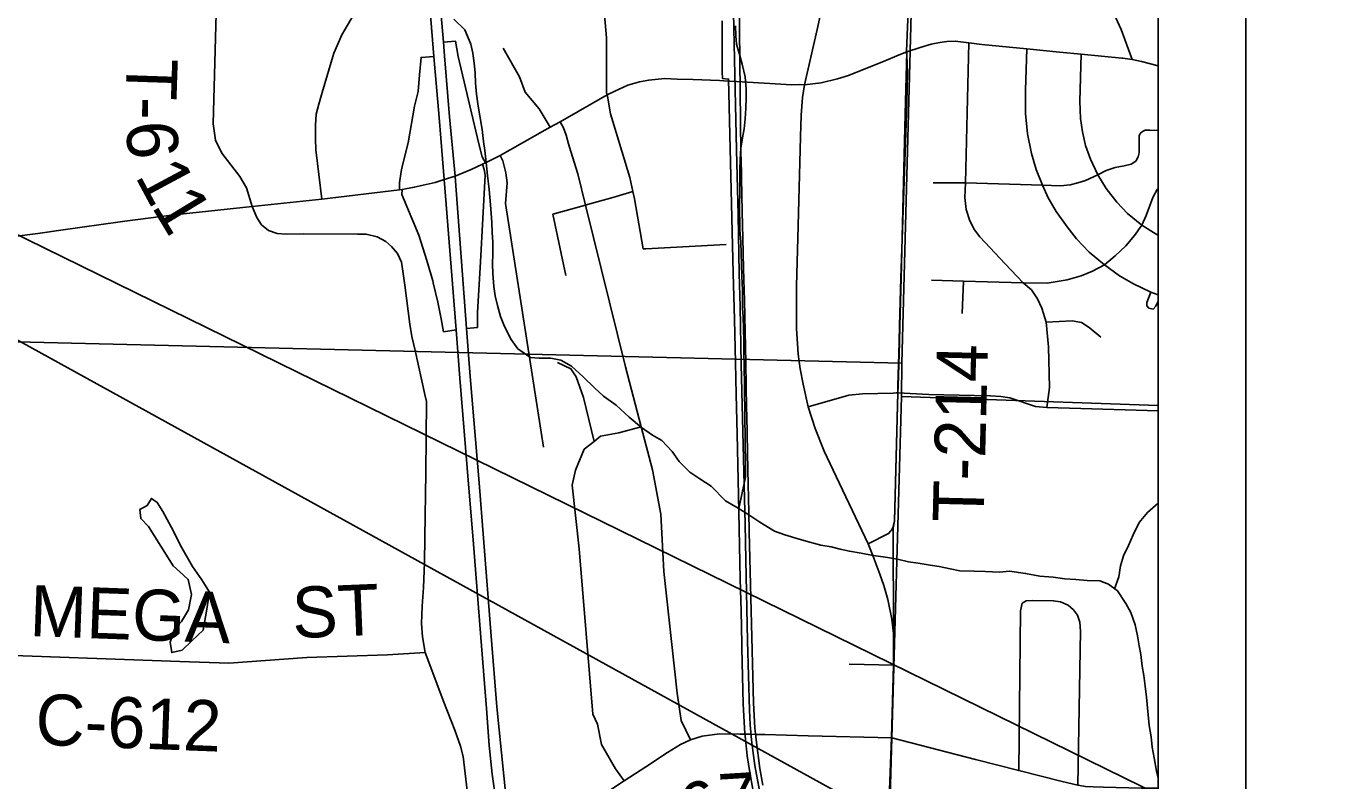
# Model space of a CAD drawing. Extents: x 0 to 34, y 0 to 22.
# Drawn here: x 8.376 to 9.827, y 18.372 to 19.213 of the extents above; entities that cross this region are included whole.
import ezdxf

# ---------------------------------------------------------------- set-up
doc = ezdxf.new("R2010")
doc.units = 0
for name, color, linetype in [('GM_X_City_Street', 7, 'Continuous'), ('GM_X_Corporation', 7, 'Continuous'), ('GM_X_County_Road', 7, 'Continuous'), ('GM_X_County_Road_Text', 7, 'Continuous'), ('GM_X_Interchange_Ramps', 7, 'Continuous'), ('GM_X_Interstate_Route', 7, 'Continuous'), ('GM_X_Minor_Lake', 7, 'Continuous'), ('GM_X_Minor_River', 7, 'Continuous'), ('GM_X_Rail_Line', 7, 'Continuous'), ('GM_X_Township_Road', 7, 'Continuous'), ('GM_X_Township_Road_Text', 7, 'Continuous'), ('SH_Data', 7, 'Continuous'), ('SH_Text', 7, 'Continuous')]:
    doc.layers.add(name, color=color, linetype=linetype)

msp = doc.modelspace()

# ---------------------------------------------------------------- linework, layer by layer
at = {"layer": 'GM_X_City_Street'}
msp.add_line((9.4188, 18.8933), (9.4202, 18.9294), dxfattribs=at)
for points in [[(9.5132, 18.7884), (9.516, 18.8109), (9.515, 18.8562), (9.5124, 18.8837), (9.5076, 18.899), (9.5025, 18.9094), (9.4958, 18.9195), (9.4867, 18.9274), (9.4668, 18.9487), (9.4385, 18.9785), (9.4325, 18.9864), (9.4274, 18.9964), (9.4231, 19.0089), (9.4218, 19.0224), (9.4224, 19.0387), (9.426, 19.1948)], [(9.637, 18.914), (9.6289, 18.9171), (9.6095, 18.9264), (9.5941, 18.9352), (9.5773, 18.9475), (9.5603, 18.9617), (9.546, 18.9764), (9.5356, 18.9896), (9.5235, 19.007), (9.5147, 19.0219), (9.5082, 19.0363), (9.5012, 19.0536), (9.4958, 19.0715), (9.4915, 19.0932), (9.4894, 19.1159), (9.4892, 19.1421), (9.4909, 19.1879)], [(9.637, 18.9806), (9.6348, 18.9817), (9.619, 18.9917), (9.6031, 19.0047), (9.5911, 19.0173), (9.5791, 19.0323), (9.5699, 19.0476), (9.5616, 19.065), (9.5561, 19.0803), (9.5527, 19.0957), (9.5505, 19.1103), (9.5497, 19.1296), (9.5513, 19.182)], [(9.3865, 19.0387), (9.4224, 19.0387), (9.5082, 19.0363), (9.5284, 19.0356), (9.539, 19.0365), (9.5478, 19.0386), (9.556, 19.0414), (9.5699, 19.0476), (9.5792, 19.0524), (9.5891, 19.0559), (9.5992, 19.0577), (9.6071, 19.0594), (9.6121, 19.0629), (9.6149, 19.0677), (9.6159, 19.0723), (9.6159, 19.0869), (9.6159, 19.091), (9.6172, 19.0937), (9.6196, 19.096), (9.6228, 19.0973), (9.6279, 19.0974), (9.637, 19.0972)], [(9.3847, 18.9305), (9.4202, 18.9294), (9.4867, 18.9274), (9.5133, 18.927), (9.5356, 18.9306), (9.5514, 18.9352), (9.5638, 18.9405), (9.5773, 18.9475), (9.5894, 18.9573), (9.6011, 18.9685), (9.6108, 18.98), (9.619, 18.9917), (9.6238, 19.0025), (9.6313, 19.0223), (9.6362, 19.0314), (9.637, 19.0321)], [(9.6289, 18.9171), (9.6245, 18.9053), (9.6246, 18.9018), (9.6266, 18.8993), (9.6316, 18.8982), (9.6347, 18.9015), (9.637, 18.9068)], [(9.5124, 18.8837), (9.5414, 18.8849), (9.5517, 18.8832), (9.5603, 18.8775), (9.5732, 18.8669)], [(9.4817, 18.384), (9.4837, 18.5619), (9.4854, 18.5705)], [(9.4854, 18.5705), (9.4899, 18.573), (9.4967, 18.5734), (9.5202, 18.5733), (9.5282, 18.5719), (9.5367, 18.5682), (9.5429, 18.5632)], [(9.5477, 18.3676), (9.5505, 18.5393), (9.5497, 18.5492), (9.5474, 18.5571), (9.5429, 18.5632)]]:
    msp.add_lwpolyline(points, dxfattribs=at)
at = {"layer": 'GM_X_Corporation'}
for points in [[(7.1023, 20.9204), (2.837, 20.9204), (2.837, 14.1204), (9.637, 14.1204), (9.637, 20.9204), (9.4036, 20.9204), (9.4022, 20.8667), (9.2273, 20.8723), (9.1354, 20.8749), (9.124, 20.8753), (8.9858, 20.878), (8.9676, 20.8785), (8.8663, 20.881), (8.6259, 20.8892), (8.5535, 20.8914), (8.5421, 20.8915), (8.4667, 20.8934), (8.0602, 20.9055), (7.9522, 20.9084), (7.1104, 20.9188)], [(8.3589, 19.8763), (9.3789, 19.8558), (9.3773, 19.7981), (9.3514, 18.838), (8.3333, 18.8624)], [(9.637, 18.7908), (9.637, 19.791), (9.3773, 19.7981), (9.3514, 18.838), (9.3511, 18.8009)], [(8.3333, 18.8624), (9.3514, 18.838), (9.3511, 18.8009), (9.3232, 17.8175), (8.3013, 17.8445)], [(9.637, 17.7759), (9.637, 18.7908), (9.3511, 18.8009), (9.3232, 17.8175), (9.3224, 17.7834)]]:
    msp.add_lwpolyline(points, close=True, dxfattribs=at)
for points in [[(9.637, 14.7553), (9.637, 20.8621)], [(9.3877, 20.1427), (9.3802, 19.8717), (9.377, 19.7721), (9.3757, 19.7325), (9.3706, 19.5177), (9.3568, 19.1851), (9.3573, 19.1731), (9.3575, 19.1703), (9.3577, 19.163), (9.3575, 19.1426), (9.3568, 19.1161), (9.3505, 18.9331), (9.349, 18.88), (9.3486, 18.8618), (9.3482, 18.8485), (9.3472, 18.8129), (9.347, 18.8053), (9.3432, 18.6624), (9.3419, 18.6564), (9.3421, 18.534), (9.3421, 18.502), (9.3401, 18.421), (9.3264, 18.0621)], [(9.3264, 18.0621), (9.3401, 18.421), (9.3421, 18.502), (9.3421, 18.534), (9.3419, 18.6564), (9.3432, 18.6624), (9.347, 18.8053), (9.3472, 18.8129), (9.3482, 18.8485), (9.3486, 18.8618), (9.349, 18.88), (9.3505, 18.9331), (9.3568, 19.1161), (9.3575, 19.1426), (9.3577, 19.163), (9.3575, 19.1703), (9.3573, 19.1731), (9.3568, 19.1851), (9.3706, 19.5177), (9.3757, 19.7325), (9.377, 19.7721), (9.3802, 19.8717), (9.3877, 20.1427)], [(9.1965, 18.3677), (9.1931, 18.3862), (9.1891, 18.4184), (9.1884, 18.4252), (9.1878, 18.4313), (9.1863, 18.4596), (9.1826, 18.6057), (9.1815, 18.6499), (9.181, 18.672), (9.18, 18.7186), (9.1786, 18.7797), (9.1784, 18.7876), (9.1776, 18.8382), (9.176, 18.9076), (9.1752, 18.9433), (9.1744, 18.9773), (9.1737, 19.0066), (9.1728, 19.0445), (9.1727, 19.0501), (9.1722, 19.0732), (9.1704, 19.2433)], [(9.1511, 19.2193), (9.1514, 19.1601), (9.1515, 19.1573), (9.1515, 19.155), (9.1585, 19.1544), (9.1637, 18.938), (9.1649, 18.8867), (9.1661, 18.8385), (9.1669, 18.8028), (9.168, 18.7588), (9.1695, 18.6907), (9.1715, 18.5973), (9.1723, 18.5621), (9.1731, 18.5253), (9.1732, 18.5202), (9.1739, 18.4892), (9.1745, 18.4583), (9.1761, 18.4313), (9.1766, 18.4256), (9.1773, 18.419), (9.1792, 18.4004), (9.182, 18.3819), (9.1856, 18.3635)]]:
    msp.add_lwpolyline(points, dxfattribs=at)
at = {"layer": 'GM_X_County_Road'}
for p, q in [((9.1483, 19.1526), (9.1578, 19.1522)), ((8.9597, 19.1007), (8.9709, 19.1067)), ((9.1896, 18.4243), (9.199, 18.4241))]:
    msp.add_line(p, q, dxfattribs=at)
for points in [[(9.243, 19.1481), (9.257, 19.2097), (9.2753, 19.2929), (9.2871, 19.3435), (9.2896, 19.3629), (9.2914, 19.3921), (9.2908, 19.4217), (9.2852, 19.4516), (9.2795, 19.4758), (9.2491, 19.5703), (9.234, 19.6114), (9.2257, 19.6387), (9.2108, 19.6817), (9.1967, 19.7245)], [(9.608, 19.176), (9.5958, 19.2096), (9.5815, 19.241), (9.5759, 19.2532), (9.5621, 19.2818), (9.5489, 19.3036), (9.5165, 19.3481), (9.4993, 19.3725), (9.4749, 19.4043), (9.4684, 19.4143), (9.462, 19.4248), (9.4555, 19.4373), (9.4524, 19.4454)], [(9.3486, 19.1812), (9.357, 19.1846), (9.3719, 19.1894), (9.3843, 19.1931), (9.3939, 19.195), (9.4017, 19.1962), (9.4108, 19.1965), (9.426, 19.1948), (9.4407, 19.1927), (9.4909, 19.1879), (9.5271, 19.1843)], [(9.3205, 19.1698), (9.331, 19.174), (9.3486, 19.1812)], [(9.5271, 19.1843), (9.5513, 19.182), (9.5968, 19.1777), (9.5978, 19.1775)], [(9.1673, 19.1517), (9.2288, 19.1481), (9.2373, 19.1482), (9.243, 19.1481), (9.2617, 19.1503), (9.2799, 19.1545), (9.2922, 19.1584), (9.3205, 19.1698)], [(9.5978, 19.1775), (9.608, 19.176), (9.6187, 19.1739), (9.637, 19.1691)], [(8.9709, 19.1067), (8.9908, 19.1183), (9.023, 19.1368), (9.0318, 19.141), (9.0462, 19.1474), (9.0591, 19.1513), (9.0695, 19.1533), (9.087, 19.1549), (9.101, 19.1543), (9.1187, 19.1537), (9.1483, 19.1526)], [(9.1578, 19.1522), (9.1597, 19.1521), (9.1673, 19.1517)], [(9.2359, 18.991), (9.2387, 19.0899), (9.2393, 19.114), (9.2409, 19.134), (9.243, 19.1481)], [(8.9039, 19.0693), (8.9535, 19.0974), (8.9597, 19.1007)], [(8.7946, 19.0315), (8.8082, 19.0338), (8.8316, 19.0393), (8.8414, 19.0423), (8.8536, 19.0463), (8.8716, 19.0537), (8.8844, 19.0596), (8.8876, 19.0611), (8.9039, 19.0693)], [(8.6276, 19.0124), (8.6698, 19.0167), (8.7051, 19.0206), (8.7919, 19.0311), (8.7946, 19.0315)], [(8.4857, 18.9961), (8.5407, 19.0033), (8.6276, 19.0124)], [(8.8209, 18.7158), (8.8218, 18.795), (8.8198, 18.8031), (8.8091, 18.8519), (8.8056, 18.8676), (8.8034, 18.8812), (8.7977, 18.9247), (8.7955, 18.9405), (8.7938, 18.9505), (8.7894, 18.9602), (8.7828, 18.9679), (8.7765, 18.9735), (8.7669, 18.9785), (8.7546, 18.9814), (8.745, 18.9816), (8.6842, 18.9818), (8.6656, 18.9816), (8.6553, 18.9825), (8.6456, 18.9856), (8.6378, 18.9921), (8.6328, 19.0002), (8.6276, 19.0124)], [(8.3327, 18.9754), (8.3888, 18.9824), (8.417, 18.9864), (8.4806, 18.9955), (8.4857, 18.9961)], [(9.319, 18.6238), (9.314, 18.6366), (9.3035, 18.6584), (9.2782, 18.7117), (9.2649, 18.7397), (9.2551, 18.765), (9.2473, 18.7894), (9.2415, 18.8144), (9.2383, 18.8314), (9.236, 18.8478), (9.2341, 18.8766), (9.2341, 18.9235), (9.2359, 18.991)], [(8.8752, 18.3068), (8.8672, 18.3619), (8.8625, 18.3998), (8.8597, 18.4111), (8.8534, 18.4289), (8.8412, 18.4603), (8.8205, 18.5154), (8.8175, 18.533), (8.8161, 18.548), (8.817, 18.5673), (8.8185, 18.588), (8.8196, 18.6158), (8.82, 18.6436), (8.8209, 18.7158)], [(9.3268, 18.0667), (9.3403, 18.4205), (9.3424, 18.5015), (9.3424, 18.5335), (9.3404, 18.5527), (9.336, 18.5745), (9.3314, 18.5903), (9.3271, 18.6029), (9.319, 18.6238)], [(8.3203, 18.5138), (8.5469, 18.5054), (8.6014, 18.5035), (8.6885, 18.51), (8.7785, 18.5129), (8.8205, 18.5154)], [(8.8752, 18.3068), (8.9039, 18.3157), (8.9154, 18.3192), (8.9766, 18.3375), (8.9966, 18.3444), (9.0112, 18.3522), (9.0421, 18.3726), (9.0662, 18.3883), (9.0904, 18.4041), (9.1049, 18.4132), (9.1159, 18.4183), (9.1291, 18.4224), (9.1482, 18.425), (9.1708, 18.4247)], [(9.1708, 18.4247), (9.182, 18.4245), (9.1896, 18.4243)], [(9.199, 18.4241), (9.2471, 18.4228), (9.3403, 18.4205)], [(9.3403, 18.4205), (9.4334, 18.3962), (9.4817, 18.384), (9.5302, 18.3718), (9.5477, 18.3676), (9.5562, 18.3663), (9.5646, 18.3658), (9.5762, 18.3656), (9.6184, 18.3646), (9.637, 18.3645)]]:
    msp.add_lwpolyline(points, dxfattribs=at)
at = {"layer": 'GM_X_Interchange_Ramps'}
for points in [[(8.8876, 19.0611), (8.884, 19.0677), (8.88, 19.0822), (8.8572, 19.1794), (8.8541, 19.1967), (8.8406, 19.1954)], [(8.8301, 19.1795), (8.8158, 19.1784), (8.814, 19.159), (8.8124, 19.1405), (8.811, 19.1346)], [(8.811, 19.1346), (8.8085, 19.1241), (8.8014, 19.0835), (8.795, 19.0584), (8.7937, 19.0515), (8.7916, 19.0386), (8.7919, 19.0311)], [(8.882, 18.9508), (8.8873, 19.0473), (8.8861, 19.0538), (8.8844, 19.0596)], [(8.7946, 19.0315), (8.7944, 19.0258), (8.8133, 18.9804), (8.8223, 18.9521), (8.8288, 18.9295), (8.8293, 18.9273)], [(8.8664, 18.8766), (8.8786, 18.8777), (8.8788, 18.8945), (8.882, 18.9508)], [(8.8293, 18.9273), (8.8344, 18.9057), (8.8381, 18.8874), (8.8408, 18.8729), (8.8549, 18.8749)]]:
    msp.add_lwpolyline(points, dxfattribs=at)
at = {"layer": 'GM_X_Interstate_Route'}
msp.add_line((8.8664, 18.8766), (8.854, 19.0405), dxfattribs=at)
for points in [[(8.8989, 18.3509), (8.895, 18.3799), (8.8917, 18.412), (8.8886, 18.4533), (8.8825, 18.5322), (8.8739, 18.6411), (8.8688, 18.703), (8.859, 18.8212), (8.8549, 18.8749), (8.8414, 19.0423), (8.8359, 19.1114), (8.8301, 19.1795), (8.8286, 19.198), (8.824, 19.2534), (8.8197, 19.3047), (8.8144, 19.3626), (8.8108, 19.4089), (8.8041, 19.4986), (8.8011, 19.5776), (8.8006, 19.612), (8.8006, 19.6249)], [(8.8406, 19.1954), (8.8361, 19.2508), (8.8278, 19.3603), (8.8236, 19.4067), (8.819, 19.486), (8.8172, 19.5753), (8.8183, 19.61), (8.8186, 19.623)], [(8.854, 19.0405), (8.8536, 19.0463), (8.8475, 19.1123), (8.8417, 19.1804), (8.8406, 19.1954)], [(9.106, 17.7777), (9.0712, 17.8356), (9.0558, 17.866), (9.022, 17.9397), (9.0067, 17.9772), (8.9908, 18.0203), (8.9648, 18.0983), (8.9426, 18.1794), (8.9154, 18.3192), (8.913, 18.3358), (8.9105, 18.3526), (8.9001, 18.4549), (8.894, 18.5339), (8.8855, 18.6428), (8.8804, 18.7046), (8.8705, 18.8229), (8.8664, 18.8766)]]:
    msp.add_lwpolyline(points, dxfattribs=at)
at = {"layer": 'GM_X_Minor_Lake'}
for points in [[(8.5394, 18.612), (8.547, 18.6056), (8.5563, 18.597), (8.5599, 18.58), (8.5567, 18.5632), (8.5489, 18.5502), (8.5411, 18.5417), (8.5363, 18.5272), (8.538, 18.5155), (8.5494, 18.5183), (8.5602, 18.5287), (8.573, 18.5406), (8.5765, 18.5616), (8.58, 18.5829), (8.5715, 18.5965), (8.561, 18.6115), (8.5493, 18.6323), (8.5377, 18.6549), (8.5279, 18.6726), (8.5217, 18.6828), (8.5152, 18.6873), (8.5104, 18.6792), (8.5025, 18.6749), (8.5034, 18.6647), (8.5122, 18.6561)], [(8.5122, 18.6561), (8.5394, 18.612)]]:
    msp.add_lwpolyline(points, dxfattribs=at)
at = {"layer": 'GM_X_Minor_River'}
for points in [[(8.8524, 19.221), (8.8647, 19.2093), (8.8713, 19.1931), (8.8733, 19.1832), (8.875, 19.1719), (8.8759, 19.1612), (8.8764, 19.1499), (8.8777, 19.1377), (8.8794, 19.1241), (8.8814, 19.1135), (8.8838, 19.0983), (8.8855, 19.085), (8.8868, 19.0748), (8.8884, 19.0615), (8.8898, 19.0471), (8.8915, 19.0312), (8.8932, 19.0141), (8.8937, 19.0047), (8.8946, 18.9944), (8.8951, 18.983), (8.8956, 18.9732), (8.8958, 18.9595), (8.8955, 18.9485), (8.8956, 18.9379), (8.8969, 18.9234), (8.8982, 18.9128), (8.901, 18.9022), (8.9042, 18.8897), (8.9089, 18.8788), (8.9162, 18.8641), (8.9236, 18.8539), (8.9377, 18.8442), (8.9472, 18.8435), (8.9605, 18.8433), (8.9715, 18.8412)], [(9.1661, 19.2136), (9.1666, 19.2026), (9.1674, 19.1931), (9.171, 19.1806), (9.1734, 19.1708), (9.177, 19.1568), (9.1779, 19.1431), (9.178, 19.1329), (9.1778, 19.1219), (9.1768, 19.1101), (9.1758, 19.0991), (9.174, 19.0888), (9.1719, 19.0774), (9.1713, 19.0648), (9.171, 19.0534), (9.1708, 19.0402), (9.171, 19.0272), (9.1707, 19.0151), (9.1711, 18.9859), (9.172, 18.973), (9.1725, 18.9601), (9.1727, 18.9483), (9.1732, 18.9343), (9.1738, 18.9195), (9.174, 18.8993), (9.1745, 18.8895), (9.1751, 18.8766), (9.1756, 18.8625), (9.1754, 18.8481), (9.1759, 18.8379), (9.1773, 18.7232), (9.1771, 18.7107), (9.1698, 18.6758)], [(8.9715, 18.8412), (8.9833, 18.8345), (8.9964, 18.8225), (9.009, 18.8105), (9.019, 18.8011), (9.0332, 18.791), (9.0477, 18.7779), (9.0615, 18.7663), (9.0737, 18.7577), (9.0841, 18.7517), (9.0956, 18.7393), (9.1033, 18.7284), (9.1152, 18.7164), (9.1263, 18.7089), (9.1389, 18.7007), (9.1549, 18.6845)], [(9.1549, 18.6845), (9.169, 18.6763), (9.1809, 18.6689), (9.1931, 18.6607), (9.2096, 18.6507), (9.221, 18.6466), (9.237, 18.6419), (9.2488, 18.6383), (9.2614, 18.6351), (9.2728, 18.6333), (9.2827, 18.6308), (9.293, 18.6283), (9.3063, 18.6262), (9.3196, 18.6237), (9.3333, 18.6216), (9.3466, 18.6195), (9.3588, 18.6167), (9.3698, 18.6149), (9.3831, 18.6128), (9.393, 18.6114), (9.4055, 18.6086), (9.4162, 18.6065), (9.4321, 18.6063), (9.4446, 18.6057), (9.4602, 18.6052), (9.4716, 18.6061), (9.4894, 18.6037), (9.5054, 18.6005), (9.5202, 18.5996), (9.5331, 18.5978), (9.5453, 18.5969), (9.5582, 18.5959), (9.5723, 18.5953), (9.5818, 18.5917), (9.5918, 18.5842), (9.601, 18.5703), (9.6065, 18.5601), (9.6116, 18.5465), (9.6141, 18.534), (9.6161, 18.523), (9.6177, 18.5135), (9.6194, 18.5003), (9.6211, 18.49), (9.6228, 18.4779), (9.6241, 18.4657), (9.6259, 18.446), (9.6272, 18.4343), (9.6292, 18.4217), (9.6305, 18.41), (9.6326, 18.3982), (9.6351, 18.3835), (9.637, 18.3755)], [(9.5886, 18.5866), (9.5934, 18.5998), (9.5952, 18.612), (9.5984, 18.6231), (9.604, 18.6349), (9.6091, 18.6468), (9.6158, 18.6602), (9.6251, 18.6717), (9.637, 18.682)]]:
    msp.add_lwpolyline(points, dxfattribs=at)
at = {"layer": 'GM_X_Rail_Line'}
msp.add_lwpolyline([(9.1945, 18.3539), (9.1905, 18.3737), (9.1876, 18.3897), (9.1856, 18.4063), (9.1839, 18.4181), (9.1825, 18.435), (9.1817, 18.4513), (9.1794, 18.5286), (9.1776, 18.6187), (9.177, 18.6584), (9.1761, 18.6872), (9.1751, 18.7317), (9.1725, 18.8369), (9.1713, 18.9007), (9.1704, 18.9377), (9.169, 19.0032), (9.1673, 19.0755), (9.1653, 19.1591), (9.1608, 19.3675), (9.155, 19.6038), (9.1547, 19.6403), (9.1525, 19.7238), (9.1393, 20.2883)], dxfattribs=at)
at = {"layer": 'GM_X_Township_Road'}
for p, q in [((9.3553, 19.1154), (9.357, 19.1846)), ((8.9709, 19.1067), (8.9597, 19.1007)), ((9.1556, 18.9702), (9.0662, 18.9654)), ((9.3424, 18.5015), (9.2928, 18.5025))]:
    msp.add_line(p, q, dxfattribs=at)
for points in [[(8.6276, 19.0124), (8.6214, 19.0333), (8.6138, 19.0459), (8.5937, 19.0718), (8.5867, 19.0863), (8.5842, 19.1045), (8.5883, 19.2551), (8.5886, 19.2822), (8.5874, 19.2971), (8.5841, 19.3116), (8.5781, 19.3287), (8.5709, 19.3432), (8.567, 19.3616), (8.5512, 19.4464), (8.544, 19.4721), (8.5354, 19.4865), (8.5249, 19.5056), (8.5222, 19.5174), (8.5209, 19.5266), (8.5199, 19.5414), (8.5207, 19.5741), (8.5236, 19.6237), (8.5247, 19.6393)], [(9.0225, 19.1458), (9.0225, 19.1497), (9.0224, 19.2004), (9.0202, 19.2259), (9.0163, 19.391), (9.0143, 19.4905), (9.0134, 19.6015)], [(8.7051, 19.0206), (8.6985, 19.0756), (8.6982, 19.0878), (8.6982, 19.103), (8.6988, 19.1152), (8.7017, 19.1263), (8.7055, 19.1395), (8.7187, 19.1833), (8.7225, 19.1924), (8.7275, 19.2037), (8.7477, 19.2377), (8.7703, 19.2755), (8.7782, 19.2929), (8.7836, 19.3089), (8.7844, 19.3549)], [(8.9597, 19.1007), (8.9472, 19.1212), (8.9317, 19.1396), (8.9255, 19.157), (8.9072, 19.1888)], [(9.0662, 18.9654), (9.0632, 18.9653), (9.0537, 19.0211), (9.0519, 19.0292), (9.0484, 19.0447), (9.027, 19.1157), (9.0239, 19.1332), (9.023, 19.1368), (9.0225, 19.1389), (9.0225, 19.1458)], [(9.1159, 18.4183), (9.1057, 18.4398), (9.101, 18.4702), (9.0863, 18.6059), (9.083, 18.6695), (9.0738, 18.7192), (9.0612, 18.7668), (9.0435, 18.8338), (8.9991, 19.014), (8.9905, 19.0488), (8.9827, 19.0737), (8.9801, 19.0823), (8.9773, 19.0918), (8.9745, 19.1002), (8.9709, 19.1067)], [(9.3394, 18.651), (9.3401, 18.6517), (9.3421, 18.6558), (9.3434, 18.6618), (9.3472, 18.8048), (9.3475, 18.8123), (9.3484, 18.8479), (9.3488, 18.8612), (9.3492, 18.8794), (9.3507, 18.9325), (9.3553, 19.1154)], [(8.9039, 19.0693), (8.907, 19.0632), (8.9103, 19.0499), (8.9116, 19.0386), (8.91, 19.0156), (8.9523, 18.7444)], [(8.9769, 18.9357), (8.9626, 19.0038), (8.9991, 19.014), (9.0014, 19.0146), (9.0295, 19.0225), (9.0519, 19.0292)], [(9.0085, 18.7508), (8.9966, 18.7995), (8.9885, 18.8225), (8.9828, 18.8317), (8.9678, 18.8386)], [(9.2473, 18.7894), (9.2926, 18.8022), (9.3075, 18.8038), (9.3417, 18.8046), (9.345, 18.8047)], [(9.345, 18.8047), (9.3472, 18.8048), (9.3816, 18.8031), (9.4321, 18.802), (9.4504, 18.8016), (9.4618, 18.8007), (9.4717, 18.7992), (9.5006, 18.7897), (9.5132, 18.7884), (9.5509, 18.7875), (9.637, 18.7848)], [(9.0421, 18.3726), (9.0323, 18.386), (9.017, 18.4131), (9.0124, 18.4358), (9.0071, 18.447), (8.9919, 18.6309), (8.9843, 18.7019), (8.9879, 18.7188), (8.9974, 18.742), (9.0085, 18.7508), (9.0158, 18.7566), (9.036, 18.7604), (9.0612, 18.7668)], [(9.314, 18.6366), (9.3368, 18.648), (9.3394, 18.651)]]:
    msp.add_lwpolyline(points, dxfattribs=at)
at = {"layer": 'SH_Data'}
msp.add_line((9.7349, 21.0001), (9.7349, 14.0001), dxfattribs=at)
at = {"layer": 'SH_Text'}
msp.add_lwpolyline([(10.6613, 17.855), (6.4321, 19.9298), (10.6613, 17.5984)], close=True, dxfattribs=at)

# ---------------------------------------------------------------- texts
at = {"layer": 'GM_X_County_Road_Text'}
for s, height, rotation, p in [('MEGA', 0.05682, 357.8965, (8.379, 18.534)), ('ST', 0.05682, 2.3661, (8.6732, 18.5314)), ('C-612', 0.05682, 357.7976, (8.3853, 18.413)), ('7', 0.0568, 3.4523, (9.1485, 18.3232)), ('6', 0.0568, 26.1485, (9.1228, 18.3093))]:
    msp.add_text(s, height=height, rotation=rotation, dxfattribs=at).set_placement(p)
at = {"layer": 'GM_X_Township_Road_Text'}
for s, height, rotation, p in [('T', 0.0568, 268.0754, (8.488, 19.1784)), ('-', 0.0568, 269.0372, (8.4865, 19.1349)), ('6', 0.0568, 274.8854, (8.4864, 19.1053)), ('1', 0.0568, 298.2526, (8.4965, 19.0463)), ('1', 0.0568, 301.2303, (8.5147, 19.0127)), ('T-214', 0.05682, 88.5994, (9.4426, 18.6602))]:
    msp.add_text(s, height=height, rotation=rotation, dxfattribs=at).set_placement(p)

doc.saveas('drawing.dxf')
